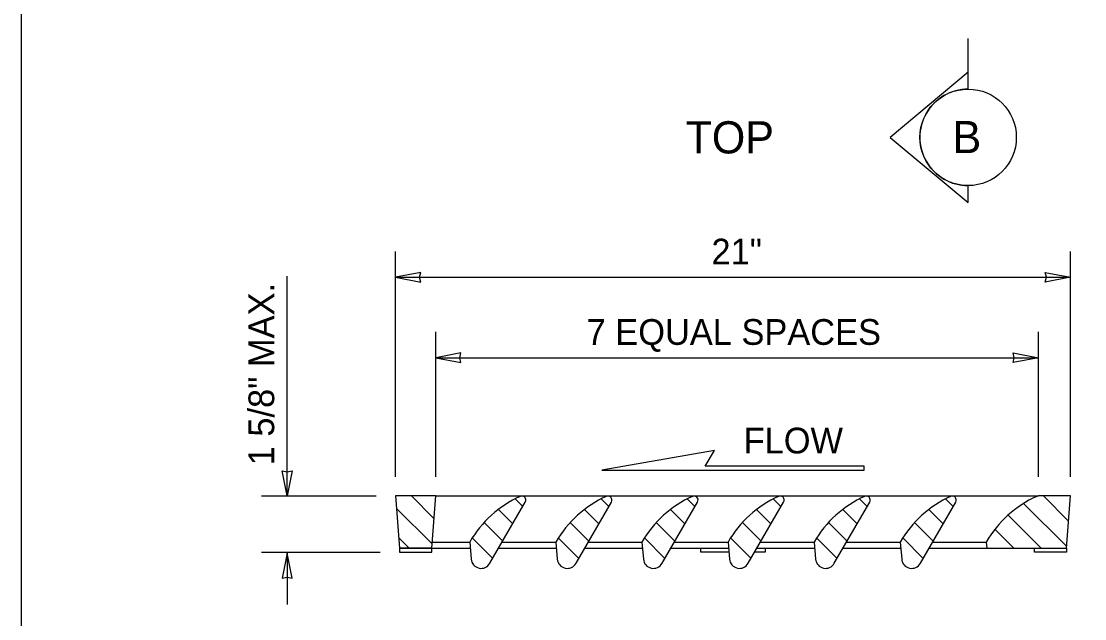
# Model space of a CAD drawing. Extents: x 99862 to 103151, y 100000 to 102076.
# Drawn here: x 99862 to 100524, y 101197 to 101569 of the extents above; entities that cross this region are included whole.
import ezdxf

# ---------------------------------------------------------------- set-up
doc = ezdxf.new("R2010")
doc.units = 0
for name, color, linetype in [('Level 1', 7, 'Continuous'), ('Level 11', 7, 'Continuous'), ('Level 15', 7, 'Continuous'), ('Level 17', 7, 'Continuous'), ('Level 2', 7, 'Continuous'), ('Level 20', 7, 'Continuous'), ('Level 3', 7, 'Continuous'), ('Level 9', 7, 'Continuous')]:
    doc.layers.add(name, color=color, linetype=linetype)

msp = doc.modelspace()

# ---------------------------------------------------------------- linework, layer by layer
at = {"layer": 'Level 1'}
for p, q in [((100119.87, 101273.68), (100494.87, 101273.68)), ((100117.66, 101245.04), (100141.02, 101245.04)), ((100161.23, 101245.04), (100194.6, 101245.04)), ((100214.8, 101245.04), (100248.17, 101245.04)), ((100268.37, 101245.04), (100301.74, 101245.04)), ((100321.94, 101245.04), (100355.31, 101245.04)), ((100375.52, 101245.04), (100408.88, 101245.04)), ((100429.09, 101245.04), (100462.45, 101245.04)), ((100117.37, 101241.18), (100141.36, 101241.18)), ((100159.01, 101241.18), (100194.93, 101241.18)), ((100212.58, 101241.18), (100248.5, 101241.18)), ((100266.15, 101241.18), (100302.07, 101241.18)), ((100319.72, 101241.18), (100355.65, 101241.18)), ((100373.29, 101241.18), (100409.22, 101241.18)), ((100426.86, 101241.18), (100462.79, 101241.18))]:
    msp.add_line(p, q, dxfattribs=at)
msp.add_lwpolyline([(99862, 99999.5), (103151, 99999.5), (103151, 102075.5), (99862, 102075.5)], close=True, dxfattribs=at)
at = {"layer": 'Level 11'}
for points in [[(100097.37, 101238.69), (100117.37, 101238.69), (100117.37, 101241.18), (100097.37, 101241.18)], [(100512.37, 101238.69), (100492.37, 101238.69), (100492.37, 101241.18), (100512.37, 101241.18)]]:
    msp.add_lwpolyline(points, close=True, dxfattribs=at)
for points in [[(100302.29, 101238.69), (100284.85, 101238.69), (100284.85, 101241.18), (100302.07, 101241.18)], [(100319.72, 101241.18), (100324.88, 101241.18), (100324.88, 101238.69), (100318.28, 101238.69)]]:
    msp.add_lwpolyline(points, dxfattribs=at)
at = {"layer": 'Level 15'}
for p, q in [((100094.87, 101285.68), (100094.87, 101425.68)), ((100514.87, 101285.68), (100514.87, 101425.68)), ((100027.37, 101273.68), (100027.37, 101410.3)), ((100094.87, 101409.68), (100514.87, 101409.68)), ((100119.87, 101285.68), (100119.87, 101375.68)), ((100494.87, 101285.68), (100494.87, 101375.68)), ((100119.87, 101359.68), (100494.87, 101359.68)), ((100011.37, 101273.68), (100082.87, 101273.68)), ((100011.37, 101238.69), (100085.37, 101238.69)), ((100027.37, 101238.21), (100027.37, 101206.21))]:
    msp.add_line(p, q, dxfattribs=at)
for points in [[(100094.87, 101409.68), (100110.59, 101406.6), (100109.86, 101409.68), (100110.59, 101412.77)], [(100514.87, 101409.68), (100499.14, 101406.6), (100499.87, 101409.68), (100499.14, 101412.77)], [(100119.87, 101359.68), (100135.59, 101356.6), (100134.87, 101359.68), (100135.59, 101362.77)], [(100494.87, 101359.68), (100479.14, 101356.6), (100479.87, 101359.68), (100479.14, 101362.77)], [(100027.37, 101273.68), (100024.28, 101289.41), (100027.37, 101288.68), (100030.45, 101289.41)], [(100027.37, 101238.21), (100024.28, 101222.48), (100027.37, 101223.21), (100030.45, 101222.48)]]:
    msp.add_lwpolyline(points, close=True, dxfattribs=at)
at = {"layer": 'Level 17'}
for p, q in [((100118.79, 101259.64), (100104.75, 101273.68)), ((100173.98, 101267.12), (100169.21, 101271.9)), ((100227.55, 101267.12), (100222.78, 101271.9)), ((100281.12, 101267.12), (100276.35, 101271.9)), ((100334.7, 101267.12), (100329.92, 101271.9)), ((100388.27, 101267.12), (100383.49, 101271.9)), ((100441.84, 101267.12), (100437.06, 101271.9)), ((100513.67, 101258.06), (100498.04, 101273.68)), ((100117.58, 101243.88), (100095.46, 101266)), ((100167.77, 101256.36), (100158.84, 101265.29)), ((100221.34, 101256.36), (100212.41, 101265.29)), ((100274.91, 101256.36), (100265.98, 101265.29)), ((100328.48, 101256.36), (100319.56, 101265.29)), ((100382.06, 101256.36), (100373.13, 101265.29)), ((100435.63, 101256.36), (100426.7, 101265.29)), ((100512.45, 101242.3), (100485.69, 101269.07)), ((100496.6, 101241.18), (100476.03, 101261.76)), ((100161.56, 101245.6), (100149.98, 101257.18)), ((100215.13, 101245.6), (100203.55, 101257.18)), ((100268.7, 101245.6), (100257.12, 101257.18)), ((100322.27, 101245.6), (100310.7, 101257.18)), ((100375.84, 101245.6), (100364.27, 101257.18)), ((100429.41, 101245.6), (100417.84, 101257.18)), ((100479.63, 101241.18), (100467.84, 101252.98)), ((100103.3, 101241.18), (100096.87, 101247.62)), ((100155.35, 101234.85), (100142.59, 101247.6)), ((100208.92, 101234.85), (100196.16, 101247.6)), ((100262.49, 101234.85), (100249.73, 101247.6)), ((100316.06, 101234.85), (100303.31, 101247.6)), ((100369.63, 101234.85), (100356.88, 101247.6)), ((100423.2, 101234.85), (100410.45, 101247.6))]:
    msp.add_line(p, q, dxfattribs=at)
at = {"layer": 'Level 2'}
for points in [[(100117.37, 101241.18), (100119.87, 101273.68), (100094.87, 101273.68), (100097.37, 101241.18), (100117.37, 101241.18)], [(100462.45, 101245.04), (100462.79, 101241.18), (100512.37, 101241.18), (100514.87, 101273.68), (100494.87, 101273.68)], [(100153.59, 101231.81), (100175.61, 101269.93)], [(100207.17, 101231.81), (100229.18, 101269.93)], [(100260.74, 101231.81), (100282.75, 101269.93)], [(100314.31, 101231.81), (100336.32, 101269.93)], [(100367.88, 101231.81), (100389.89, 101269.93)], [(100421.45, 101231.81), (100443.46, 101269.93)], [(100141.02, 101245.04), (100141.96, 101234.39)], [(100194.6, 101245.04), (100195.53, 101234.39)], [(100248.17, 101245.04), (100249.1, 101234.39)], [(100301.74, 101245.04), (100302.67, 101234.39)], [(100355.31, 101245.04), (100356.24, 101234.39)], [(100408.88, 101245.04), (100409.81, 101234.39)]]:
    msp.add_lwpolyline(points, dxfattribs=at)
for centre, radius, start, end in [((100201.51, 101209.8), 70, 114.56824, 149.77152), ((100173.44, 101271.18), 2.5, 330, 114.56824), ((100255.08, 101209.8), 70, 114.56824, 149.77152), ((100227.01, 101271.18), 2.5, 330, 114.56824), ((100308.65, 101209.8), 70, 114.56824, 149.77152), ((100280.58, 101271.18), 2.5, 330, 114.56824), ((100362.22, 101209.8), 70, 114.56824, 149.77152), ((100334.15, 101271.18), 2.5, 330, 114.56824), ((100415.79, 101209.8), 70, 114.56824, 149.77152), ((100387.73, 101271.18), 2.5, 330, 114.56824), ((100469.36, 101209.8), 70, 114.56824, 149.77152), ((100441.3, 101271.18), 2.5, 330, 114.56824), ((100522.93, 101209.8), 70, 114.56824, 149.77152), ((100494.87, 101271.18), 2.5, 90, 114.56824), ((100148.18, 101234.93), 6.25, 185, 330), ((100201.75, 101234.93), 6.25, 185, 330), ((100255.32, 101234.93), 6.25, 185, 330), ((100308.9, 101234.93), 6.25, 185, 330), ((100362.47, 101234.93), 6.25, 185, 330), ((100416.04, 101234.93), 6.25, 185, 330)]:
    msp.add_arc(centre, radius, start, end, dxfattribs=at)
at = {"layer": 'Level 3'}
msp.add_lwpolyline([(100386.44, 101292.16), (100287.56, 101292.16), (100293.26, 101302.02), (100223.29, 101289.68), (100386.44, 101289.68)], close=True, dxfattribs=at)
at = {"layer": 'Level 9'}
for p, q in [((100451.12, 101528.28), (100451.12, 101558.28)), ((100451.12, 101537.32), (100402.65, 101496.72)), ((100451.12, 101526.72), (100451.12, 101537.32)), ((100402.65, 101496.72), (100451.12, 101456.12)), ((100451.12, 101456.12), (100451.12, 101466.72))]:
    msp.add_line(p, q, dxfattribs=at)
msp.add_circle((100451.12, 101496.72), 30, dxfattribs=at)
msp.add_arc((100451.12, 101496.72), 30, 89.99779, 270.00221, dxfattribs=at)

# ---------------------------------------------------------------- texts
at = {"layer": 'Level 20'}
for s, height, p in [('TOP', 20, (100275.34, 101486.72)), ('B', 20, (100441.47, 101486.9)), ('FLOW', 16, (100311.47, 101300.16))]:
    msp.add_text(s, height=height, dxfattribs=at).set_placement(p)
for s, rotation, p in [('21"', 360, (100291.46, 101417.68)), ('1 5/8" MAX.', 90, (100019.37, 101292.73)), ('7 EQUAL SPACES', 360, (100213.78, 101367.68))]:
    msp.add_text(s, height=16, rotation=rotation, dxfattribs=at).set_placement(p)

doc.saveas('drawing.dxf')
